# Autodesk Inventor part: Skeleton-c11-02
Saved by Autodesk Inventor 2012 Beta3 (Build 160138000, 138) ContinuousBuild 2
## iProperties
Created: 2011-01
Part Number: Skeleton-c11-02
Material: Default
Document SubType Name: Modeling
Designer: Beta-8540w
Density: 1 g/cm^3
_SkeletonDoc: Frame Skeleton File
_Version: 15.0.0
Author: Beta-8540w
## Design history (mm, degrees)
sketch "Reference Skeleton"
